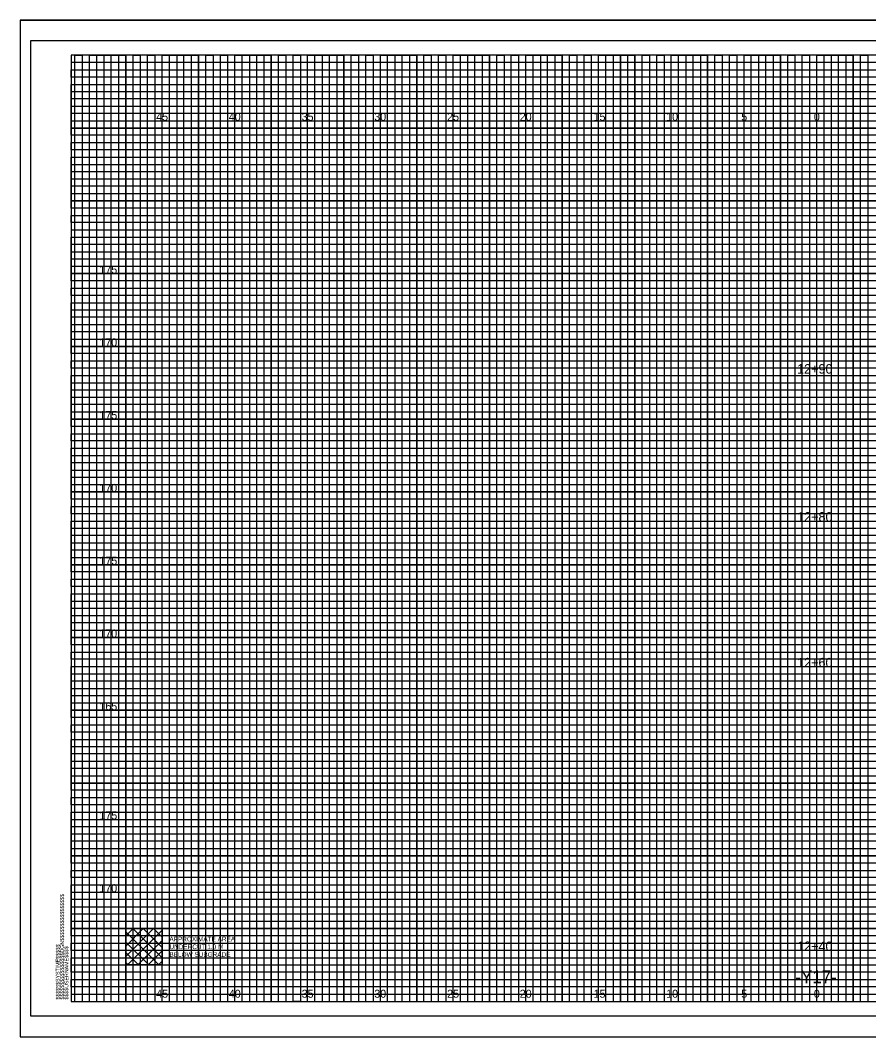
# Model space of a CAD drawing. Extents: x -4 to 103, y -2 to 209.
# Drawn here: x -3.5 to 54.8, y 139.2 to 209.1 of the extents above; entities that cross this region are included whole.
import ezdxf

# ---------------------------------------------------------------- set-up
doc = ezdxf.new("R2010")
doc.units = 0
for name, color, linetype in [('Default', 7, 'Continuous'), ('Prop XS Alignment Label', 7, 'Continuous'), ('Prop XS Elevation Labels', 7, 'Continuous'), ('Prop XS Offset Labels', 7, 'Continuous'), ('Prop XS Station Labels', 7, 'Continuous'), ('Prop XS Undercut Exc Hatch', 7, 'Continuous'), ('Sheet Cross Section CELL', 7, 'Continuous'), ('Sheet Cross Section Grid Major CELL', 7, 'Continuous'), ('Sheet Cross Section Grid Middle CELL', 7, 'Continuous'), ('Sheet Cutting Line CELL', 7, 'Continuous'), ('Sheet DOT Grid CELL', 7, 'Continuous'), ('Sheet Plot Border Inside CELL', 7, 'Continuous'), ('Sheet Plot Border Outside CELL', 7, 'Continuous')]:
    doc.layers.add(name, color=color, linetype=linetype)

msp = doc.modelspace()

# ---------------------------------------------------------------- linework, layer by layer
at = {"layer": 'Default'}
msp.add_lwpolyline([(3.75, 146.65), (6.25, 146.65), (6.25, 144.15), (3.75, 144.15)], close=True, dxfattribs=at)
at = {"layer": 'Prop XS Undercut Exc Hatch'}
for p, q in [((3.75, 146.15237), (4.24763, 146.65)), ((3.75, 145.44526), (4.95474, 146.65)), ((3.75, 144.73816), (5.66184, 146.65)), ((4.23998, 146.65), (6.25, 144.63998)), ((4.94709, 146.65), (6.25, 145.34709)), ((5.6542, 146.65), (6.25, 146.0542)), ((3.75, 146.43288), (6.03288, 144.15)), ((3.86895, 144.15), (6.25, 146.53105)), ((3.75, 145.72577), (5.32577, 144.15)), ((4.57606, 144.15), (6.25, 145.82394)), ((3.75, 145.01866), (4.61866, 144.15)), ((5.28316, 144.15), (6.25, 145.11684)), ((3.75, 144.31156), (3.91156, 144.15)), ((5.99027, 144.15), (6.25, 144.40973))]:
    msp.add_line(p, q, dxfattribs=at)
at = {"layer": 'Sheet Cross Section CELL'}
msp.add_lwpolyline([(102.5, 206.65), (0, 206.65), (0, 141.65), (102.5, 141.65)], close=True, dxfattribs=at)
at = {"layer": 'Sheet Cross Section Grid Major CELL'}
for points in [[(1.25, 141.65), (1.25, 206.65), (3.75, 206.65), (3.75, 141.65), (6.25, 141.65), (6.25, 206.65), (8.75, 206.65), (8.75, 141.65), (11.25, 141.65), (11.25, 206.65), (13.75, 206.65), (13.75, 141.65), (16.25, 141.65), (16.25, 206.65), (18.75, 206.65), (18.75, 141.65), (21.25, 141.65), (21.25, 206.65), (23.75, 206.65), (23.75, 141.65), (26.25, 141.65), (26.25, 206.65), (28.75, 206.65), (28.75, 141.65), (31.25, 141.65), (31.25, 206.65), (33.75, 206.65), (33.75, 141.65), (36.25, 141.65), (36.25, 206.65), (38.75, 206.65), (38.75, 141.65), (41.25, 141.65), (41.25, 206.65), (43.75, 206.65), (43.75, 141.65), (46.25, 141.65), (46.25, 206.65), (48.75, 206.65), (48.75, 141.65), (51.25, 141.65), (51.25, 206.65), (53.75, 206.65), (53.75, 141.65)], [(102.5, 201.65), (0, 201.65), (0, 204.15), (74.25, 204.15)], [(102.5, 196.65), (0, 196.65), (0, 199.15), (102.5, 199.15)], [(102.5, 191.65), (0, 191.65), (0, 194.15), (102.5, 194.15)], [(102.5, 186.65), (0, 186.65), (0, 189.15), (102.5, 189.15)], [(102.5, 181.65), (0, 181.65), (0, 184.15), (102.5, 184.15)], [(102.5, 176.65), (0, 176.65), (0, 179.15), (102.5, 179.15)], [(102.5, 171.65), (0, 171.65), (0, 174.15), (102.5, 174.15)], [(102.5, 166.65), (0, 166.65), (0, 169.15), (102.5, 169.15)], [(102.5, 161.65), (0, 161.65), (0, 164.15), (102.5, 164.15)], [(102.5, 156.65), (0, 156.65), (0, 159.15), (102.5, 159.15)], [(102.5, 151.65), (0, 151.65), (0, 154.15), (102.5, 154.15)], [(102.5, 146.65), (0, 146.65), (0, 149.15), (102.5, 149.15)], [(0, 144.15), (102.5, 144.15)]]:
    msp.add_lwpolyline(points, dxfattribs=at)
at = {"layer": 'Sheet Cross Section Grid Middle CELL'}
for points in [[(0, 203.65), (0, 204.65), (74.25, 204.65), (74.25, 205.15), (0, 205.15), (0, 205.65), (74.25, 205.65), (74.25, 206.15), (0, 206.15)], [(0.25, 141.65), (0.25, 206.65), (0.75, 206.65), (0.75, 141.65), (1.75, 141.65), (1.75, 206.65), (2.25, 206.65), (2.25, 141.65), (2.75, 141.65), (2.75, 206.65), (3.25, 206.65), (3.25, 141.65), (4.25, 141.65), (4.25, 206.65), (4.75, 206.65), (4.75, 141.65), (5.25, 141.65), (5.25, 206.65), (5.75, 206.65), (5.75, 141.65), (6.75, 141.65), (6.75, 206.65), (7.25, 206.65), (7.25, 141.65), (7.75, 141.65), (7.75, 206.65), (8.25, 206.65), (8.25, 141.65), (9.25, 141.65), (9.25, 206.65), (9.75, 206.65), (9.75, 141.65), (10.25, 141.65), (10.25, 206.65), (10.75, 206.65), (10.75, 141.65), (11.75, 141.65), (11.75, 206.65), (12.25, 206.65), (12.25, 141.65), (12.75, 141.65), (12.75, 206.65), (13.25, 206.65), (13.25, 141.65), (14.25, 141.65), (14.25, 206.65), (14.75, 206.65), (14.75, 141.65), (15.75, 141.65), (15.25, 141.65), (15.25, 206.65), (15.75, 206.65), (15.75, 141.65), (16.75, 141.65), (16.75, 206.65), (17.25, 206.65), (17.25, 141.65), (17.75, 141.65), (17.75, 206.65), (18.25, 206.65), (18.25, 141.65), (19.25, 141.65), (19.25, 206.65), (19.75, 206.65), (19.75, 141.65), (20.25, 141.65), (20.25, 206.65), (20.75, 206.65), (20.75, 141.65), (21.75, 141.65), (21.75, 206.65), (22.25, 206.65), (22.25, 141.65), (22.75, 141.65), (22.75, 206.65), (23.25, 206.65), (23.25, 141.65), (24.25, 141.65), (24.25, 206.65), (24.75, 206.65), (24.75, 141.65), (25.25, 141.65), (25.25, 206.65), (25.75, 206.65), (25.75, 141.65), (26.75, 141.65), (26.75, 206.65), (27.25, 206.65), (27.25, 141.65), (27.75, 141.65), (27.75, 206.65), (28.25, 206.65), (28.25, 141.65), (29.25, 141.65), (29.25, 206.65), (29.75, 206.65), (29.75, 141.65), (30.25, 141.65), (30.25, 206.65), (30.75, 206.65), (30.75, 141.65)], [(30.75, 141.65), (31.75, 141.65), (31.75, 206.65), (32.25, 206.65), (32.25, 141.65), (32.75, 141.65), (32.75, 206.65), (33.25, 206.65), (33.25, 141.65), (34.25, 141.65), (34.25, 206.65), (34.75, 206.65), (34.75, 141.65), (35.25, 141.65), (35.25, 206.65), (35.75, 206.65), (35.75, 141.65), (36.75, 141.65), (36.75, 206.65), (37.25, 206.65), (37.25, 141.65), (37.75, 141.65), (37.75, 206.65), (37.75, 141.65)], [(38.25, 206.65), (38.25, 141.65), (39.25, 141.65), (39.25, 206.65), (39.75, 206.65), (39.75, 141.65), (40.25, 141.65), (40.25, 206.65), (40.75, 206.65), (40.75, 141.65), (41.75, 141.65), (41.75, 206.65), (42.25, 206.65), (42.25, 141.65), (42.75, 141.65), (42.75, 206.65), (43.25, 206.65), (43.25, 141.65), (43.75, 141.65), (44.25, 141.65), (44.25, 206.65), (44.75, 206.65), (44.75, 141.65), (45.25, 141.65), (45.25, 206.65), (45.75, 206.65), (45.75, 141.65), (46.75, 141.65), (46.75, 206.65), (47.25, 206.65), (47.25, 141.65), (47.75, 141.65), (47.75, 206.65), (48.25, 206.65), (48.25, 141.65), (49.25, 141.65), (49.25, 206.65), (49.75, 206.65), (49.75, 141.65), (50.25, 141.65), (50.25, 206.65), (50.75, 206.65), (50.75, 141.65), (51.75, 141.65), (51.75, 206.65), (52.25, 206.65), (52.25, 141.65), (52.75, 141.65), (52.75, 206.65), (53.25, 206.65), (53.25, 141.65), (54.25, 141.65), (54.25, 206.65), (54.75, 206.65), (54.75, 141.65), (55.25, 141.65)], [(102.5, 203.65), (0, 203.65)], [(102.5, 202.65), (0, 202.65), (0, 203.15), (102.5, 203.15)], [(102.5, 201.15), (0, 201.15), (0, 202.15), (102.5, 202.15)], [(102.5, 200.15), (0, 200.15), (0, 200.65), (102.5, 200.65)], [(102.5, 198.65), (0, 198.65), (0, 199.65), (102.5, 199.65)], [(102.5, 197.65), (0, 197.65), (0, 198.15), (102.5, 198.15)], [(102.5, 196.15), (0, 196.15), (0, 197.15), (102.5, 197.15)], [(102.5, 195.15), (0, 195.15), (0, 195.65), (102.5, 195.65)], [(0, 194.65), (102.5, 194.65)], [(102.5, 193.65), (0, 193.65)], [(102.5, 192.65), (0, 192.65), (0, 193.15), (102.5, 193.15)], [(102.5, 191.15), (0, 191.15), (0, 192.15), (102.5, 192.15)], [(102.5, 190.15), (0, 190.15), (0, 190.65), (102.5, 190.65)], [(102.5, 188.65), (0, 188.65), (0, 189.65), (102.5, 189.65)], [(102.5, 187.65), (0, 187.65), (0, 188.15), (102.5, 188.15)], [(102.5, 186.15), (0, 186.15), (0, 187.15), (102.5, 187.15)], [(102.5, 185.15), (0, 185.15), (0, 185.65), (102.5, 185.65)], [(102.5, 183.65), (0, 183.65), (0, 184.65), (102.5, 184.65)], [(102.5, 182.65), (0, 182.65), (0, 183.15), (102.5, 183.15)], [(102.5, 181.15), (0, 181.15), (0, 182.15), (102.5, 182.15)], [(102.5, 180.15), (0, 180.15), (0, 180.65), (102.5, 180.65)], [(102.5, 178.65), (0, 178.65), (0, 179.65), (102.5, 179.65)], [(102.5, 177.65), (0, 177.65), (0, 178.15), (102.5, 178.15)], [(102.5, 176.15), (0, 176.15), (0, 177.15), (102.5, 177.15)], [(102.5, 175.15), (0, 175.15), (0, 175.65), (102.5, 175.65)], [(102.5, 173.65), (0, 173.65), (0, 174.65), (102.5, 174.65)], [(102.5, 172.65), (0, 172.65), (0, 173.15)], [(0, 173.15), (102.5, 173.15)], [(102.5, 171.15), (0, 171.15), (0, 172.15), (102.5, 172.15)], [(102.5, 170.15), (0, 170.15), (0, 170.65), (102.5, 170.65)], [(102.5, 168.65), (0, 168.65), (0, 169.65), (102.5, 169.65)], [(102.5, 167.65), (0, 167.65), (0, 168.15), (102.5, 168.15)], [(102.5, 166.15), (0, 166.15), (0, 167.15), (102.5, 167.15)], [(102.5, 165.15), (0, 165.15), (0, 165.65), (102.5, 165.65)], [(102.5, 163.65), (0, 163.65), (0, 164.65), (102.5, 164.65)], [(102.5, 162.65), (0, 162.65), (0, 163.15), (102.5, 163.15)], [(102.5, 161.15), (0, 161.15), (0, 162.15), (102.5, 162.15)], [(102.5, 160.15), (0, 160.15), (0, 160.65), (102.5, 160.65)], [(102.5, 158.65), (0, 158.65), (0, 159.65), (102.5, 159.65)], [(102.5, 157.65), (0, 157.65), (0, 158.15), (102.5, 158.15)], [(102.5, 156.15), (0, 156.15), (0, 157.15), (102.5, 157.15)], [(102.5, 155.15), (0, 155.15), (0, 155.65), (102.5, 155.65)], [(102.5, 153.65), (0, 153.65), (0, 154.65), (102.5, 154.65)], [(102.5, 152.65), (0, 152.65), (0, 153.15), (102.5, 153.15)], [(102.5, 151.15), (0, 151.15), (0, 152.15), (102.5, 152.15)], [(102.5, 150.15), (0, 150.15), (0, 150.65), (102.5, 150.65)], [(102.5, 148.65), (0, 148.65), (0, 149.65), (102.5, 149.65)], [(102.5, 147.65), (0, 147.65), (0, 148.15), (102.5, 148.15)], [(102.5, 146.15), (0, 146.15), (0, 147.15), (102.5, 147.15)], [(102.5, 145.15), (0, 145.15), (0, 145.65), (102.5, 145.65)], [(102.5, 143.65), (0, 143.65), (0, 144.65), (102.5, 144.65)], [(102.5, 142.65), (0, 142.65), (0, 143.15), (102.5, 143.15)], [(0, 142.15), (102.5, 142.15)]]:
    msp.add_lwpolyline(points, dxfattribs=at)
at = {"layer": 'Sheet Cutting Line CELL'}
for p, q in [((-3.5, 209.05), (103.4, 209.05)), ((-3.5, 209.05), (-3.5, 139.225)), ((-3.5, 139.225), (103.4, 139.225))]:
    msp.add_line(p, q, dxfattribs=at)
at = {"layer": 'Sheet DOT Grid CELL'}
for p, q in [((1.25, 141.65), (1.25, 206.65)), ((3.75, 141.65), (3.75, 206.65)), ((6.25, 141.65), (6.25, 206.65)), ((8.75, 141.65), (8.75, 206.65)), ((11.25, 141.65), (11.25, 206.65)), ((13.75, 141.65), (13.75, 206.65)), ((16.25, 141.65), (16.25, 206.65)), ((18.75, 141.65), (18.75, 206.65)), ((21.25, 141.65), (21.25, 206.65)), ((23.75, 141.65), (23.75, 206.65)), ((26.25, 141.65), (26.25, 206.65)), ((28.75, 141.65), (28.75, 206.65)), ((31.25, 141.65), (31.25, 206.65)), ((33.75, 141.65), (33.75, 206.65)), ((36.25, 141.65), (36.25, 206.65)), ((38.75, 141.65), (38.75, 206.65)), ((41.25, 141.65), (41.25, 206.65)), ((43.75, 141.65), (43.75, 206.65)), ((46.25, 141.65), (46.25, 206.65)), ((48.75, 141.65), (48.75, 206.65)), ((51.25, 141.65), (51.25, 206.65)), ((53.75, 141.65), (53.75, 206.65)), ((0, 204.15), (74.25, 204.15)), ((0, 201.65), (102.5, 201.65)), ((0, 199.15), (102.5, 199.15)), ((0, 196.65), (102.5, 196.65)), ((0, 194.15), (102.5, 194.15)), ((0, 191.65), (102.5, 191.65)), ((0, 189.15), (102.5, 189.15)), ((0, 186.65), (102.5, 186.65)), ((0, 184.15), (102.5, 184.15)), ((0, 181.65), (102.5, 181.65)), ((0, 179.15), (102.5, 179.15)), ((0, 176.65), (102.5, 176.65)), ((0, 174.15), (102.5, 174.15)), ((0, 171.65), (102.5, 171.65)), ((0, 169.15), (102.5, 169.15)), ((0, 166.65), (102.5, 166.65)), ((0, 164.15), (102.5, 164.15)), ((0, 161.65), (102.5, 161.65)), ((0, 159.15), (102.5, 159.15)), ((0, 156.65), (102.5, 156.65)), ((0, 154.15), (102.5, 154.15)), ((0, 151.65), (102.5, 151.65)), ((0, 149.15), (102.5, 149.15)), ((0, 146.65), (102.5, 146.65)), ((0, 144.15), (102.5, 144.15))]:
    msp.add_line(p, q, dxfattribs=at)
at = {"layer": 'Sheet Plot Border Inside CELL'}
msp.add_lwpolyline([(103, 207.65), (-2.8, 207.65), (-2.8, 140.65), (103, 140.65)], close=True, dxfattribs=at)
at = {"layer": 'Sheet Plot Border Outside CELL'}
msp.add_lwpolyline([(103.4, 209.05), (-3.5, 209.05), (-3.5, 139.225), (103.4, 139.225)], close=True, dxfattribs=at)

# ---------------------------------------------------------------- texts
at = {"layer": 'Default'}
for s, p in [('APPROXIMATE AREA ', (6.75, 145.77333)), ('UNDERCUT 1.0 M', (6.75, 145.24)), ('BELOW SUBGRADE', (6.75, 144.70667))]:
    msp.add_text(s, height=0.32, dxfattribs=at).set_placement(p)
at = {"layer": 'Prop XS Alignment Label'}
msp.add_text('-Y17-', height=0.875, dxfattribs=at).set_placement((49.77311, 142.9))
at = {"layer": 'Prop XS Elevation Labels'}
for s, p in [('175', (1.93825, 191.65)), ('170', (1.92958, 186.65)), ('175', (1.93825, 181.65)), ('170', (1.92958, 176.65)), ('175', (1.93825, 171.65)), ('170', (1.92958, 166.65)), ('165', (1.93825, 161.65)), ('175', (1.93825, 154.15)), ('170', (1.92958, 149.15))]:
    msp.add_text(s, height=0.55, dxfattribs=at).set_placement(p)
at = {"layer": 'Prop XS Offset Labels'}
for s, p in [('45', (5.83992, 202.15)), ('40', (10.83125, 202.15)), ('35', (15.83992, 202.15)), ('30', (20.83125, 202.15)), ('25', (25.83992, 202.15)), ('20', (30.83125, 202.15)), ('15', (35.90575, 202.15)), ('10', (40.89708, 202.15)), ('5', (46.05742, 202.15)), ('0', (51.04875, 202.15)), ('0', (51.04875, 202.15)), ('45', (5.83992, 141.9)), ('40', (10.83125, 141.9)), ('35', (15.83992, 141.9)), ('30', (20.83125, 141.9)), ('25', (25.83992, 141.9)), ('20', (30.83125, 141.9)), ('15', (35.90575, 141.9)), ('10', (40.89708, 141.9)), ('5', (46.05742, 141.9)), ('0', (51.04875, 141.9)), ('0', (51.04875, 141.9))]:
    msp.add_text(s, height=0.55, dxfattribs=at).set_placement(p)
at = {"layer": 'Prop XS Station Labels'}
for s, p in [('12+90', (49.89337, 184.778)), ('12+80', (49.89337, 174.6094)), ('12+60', (49.89337, 164.5976)), ('12+40', (49.89337, 145.1101))]:
    msp.add_text(s, height=0.65, dxfattribs=at).set_placement(p)
at = {"layer": 'Sheet Cross Section CELL'}
for s, p in [('$$$$$$$$$$$$$$$$DGN$$$$$$$$$$$$$$$$', (-0.5, 141.775)), ('$$$$$$SYSTIME$$$$$', (-0.7973, 141.7747)), ('$$$$USERNAME$$$$', (-0.2, 141.775))]:
    msp.add_text(s, height=0.2625, rotation=90, dxfattribs=at).set_placement(p)
at = {"layer": 'Sheet Cross Section Grid Major CELL'}
msp.add_text('040397', height=0.0025, rotation=90, dxfattribs=at).set_placement((-0.0007, 206.6364))

doc.saveas('drawing.dxf')
